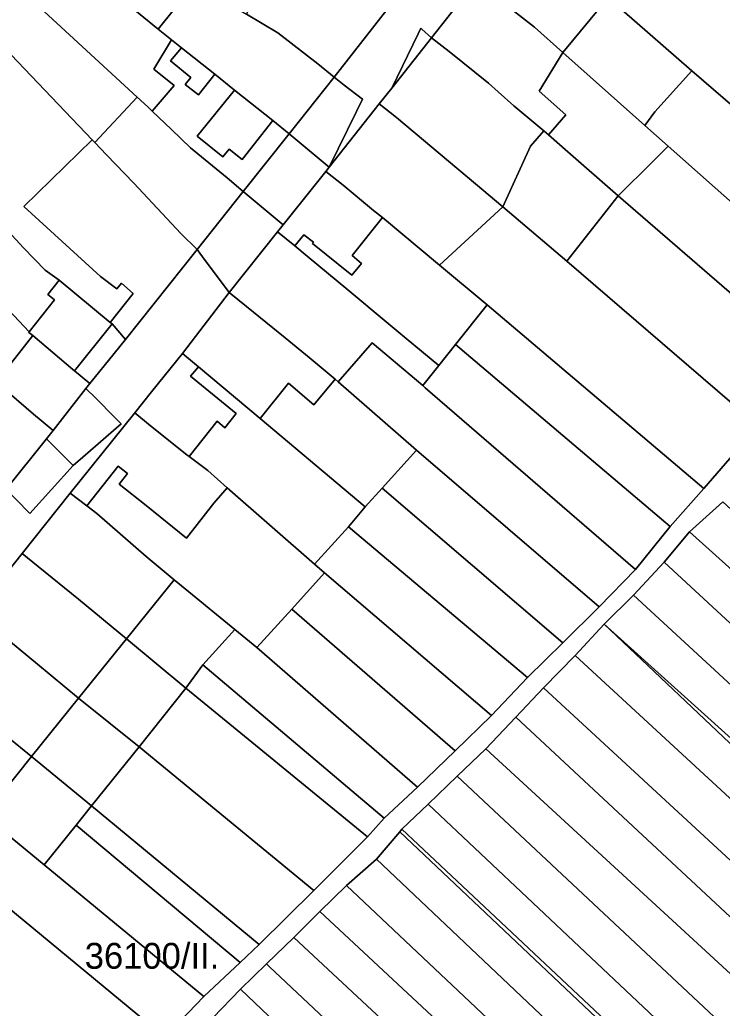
# Model space of a CAD drawing. Extents: x -537068 to -534056, y -1176840 to -1172401.
# Drawn here: x -535510.5 to -535374.6, y -1175812.5 to -1175621.4 of the extents above; entities that cross this region are included whole.
import ezdxf

# ---------------------------------------------------------------- set-up
doc = ezdxf.new("R2010")
doc.units = 0
for name, color, linetype in [('95560013', 7, 'Continuous'), ('95590013', 7, 'Continuous'), ('95610013', 7, 'Continuous'), ('95640013', 7, 'Continuous'), ('95660013', 7, 'Continuous')]:
    doc.layers.add(name, color=color, linetype=linetype)

msp = doc.modelspace()

# ---------------------------------------------------------------- linework, layer by layer
at = {"layer": '95560013'}
for points in [[(-535502.19, -1175597.34), (-535502.06, -1175597.17), (-535477.65, -1175615.63), (-535483.68, -1175623.22), (-535507.39, -1175603.91)], [(-535329.06, -1175662.73), (-535328.93, -1175662.85), (-535336.04, -1175669.84), (-535336.22, -1175669.68), (-535373.98, -1175636.94), (-535380.5, -1175631.28), (-535394.11, -1175619.48), (-535384.76, -1175608.85), (-535364.85, -1175626.56), (-535367.3, -1175629.34)], [(-535490.82, -1175672.36), (-535488.52, -1175674.32), (-535493.01, -1175679.93), (-535502.87, -1175671.76), (-535505.58, -1175669.81), (-535509.72, -1175665.5), (-535529.78, -1175643.79), (-535529.88, -1175643.69), (-535534.77, -1175638.56), (-535533.08, -1175636.42), (-535527.93, -1175629.9), (-535522.79, -1175623.39), (-535520.06, -1175619.94), (-535496.47, -1175644.61), (-535509.67, -1175657.5), (-535494.87, -1175671.04), (-535491.72, -1175673.47)], [(-535388.12, -1175648.87), (-535394.77, -1175655.48), (-535404.48, -1175646.96), (-535408.22, -1175643.69), (-535404.88, -1175639.8), (-535410.04, -1175635.24), (-535405.47, -1175627.73), (-535389.59, -1175641.84), (-535385.08, -1175645.85)], [(-535346.57, -1175680.03), (-535385.08, -1175645.85), (-535389.59, -1175641.84), (-535387.66, -1175639.2), (-535380.5, -1175631.28), (-535373.98, -1175636.94), (-535336.22, -1175669.68), (-535336.04, -1175669.84), (-535336.29, -1175670.08), (-535343.16, -1175677.96), (-535345.98, -1175680.56)], [(-535529.78, -1175643.79), (-535509.72, -1175665.5), (-535505.58, -1175669.81), (-535502.87, -1175671.76), (-535505.04, -1175674.53), (-535503.75, -1175675.55), (-535508.64, -1175681.77), (-535536.46, -1175652.23), (-535529.88, -1175643.69)], [(-535394.77, -1175655.48), (-535388.12, -1175648.87), (-535385.08, -1175645.85), (-535346.57, -1175680.03), (-535345.98, -1175680.56), (-535348.76, -1175683.14), (-535355.61, -1175689.31)], [(-535508.64, -1175681.77), (-535508.71, -1175681.86), (-535507.97, -1175682.48), (-535514.51, -1175690.8), (-535518.58, -1175686.14), (-535541.94, -1175659.8), (-535536.46, -1175652.23)], [(-535394.77, -1175655.48), (-535355.61, -1175689.31), (-535367.67, -1175699.94), (-535404.66, -1175668.06)], [(-535429.28, -1175668.86), (-535420.07, -1175676.55), (-535426.19, -1175684.18), (-535429.46, -1175688.27), (-535435.75, -1175683.03), (-535439.23, -1175680.14), (-535447.02, -1175673.66), (-535454.87, -1175667.13), (-535457.31, -1175665.14), (-535455.56, -1175662.97), (-535453.68, -1175664.42), (-535453.86, -1175664.66), (-535446.29, -1175670.81), (-535444.41, -1175668.51), (-535446.19, -1175667), (-535440.33, -1175659.64)], [(-535391.39, -1175727.68), (-535398.42, -1175734.92), (-535433.74, -1175704.6), (-535448.87, -1175691.41), (-535442.35, -1175683.85), (-535432.55, -1175692.13), (-535432.1, -1175692.57)], [(-535477.46, -1175690.33), (-535475.94, -1175688.5), (-535464.01, -1175698.5), (-535443.66, -1175715.55), (-535446.88, -1175719.44), (-535453.47, -1175726.66), (-535470.38, -1175711.9), (-535474.12, -1175708.55), (-535477.73, -1175705.86), (-535472.29, -1175699.02), (-535470.79, -1175700.28), (-535468.64, -1175697.54)], [(-535464.01, -1175698.5), (-535458.52, -1175691.68), (-535453.59, -1175695.83), (-535449.46, -1175690.92), (-535448.87, -1175691.41), (-535433.74, -1175704.6), (-535440.39, -1175711.94), (-535443.66, -1175715.55)], [(-535405.44, -1175741.83), (-535440.39, -1175711.94), (-535433.74, -1175704.6), (-535398.42, -1175734.92)], [(-535405.44, -1175741.83), (-535412.29, -1175748.56), (-535446.88, -1175719.44), (-535443.66, -1175715.55), (-535440.39, -1175711.94)], [(-535321.9, -1175763.11), (-535326.37, -1175769.45), (-535380.94, -1175720.41), (-535374.5, -1175714.58)], [(-535326.37, -1175769.45), (-535331.39, -1175776.57), (-535385.87, -1175726.27), (-535380.94, -1175720.41)], [(-535336.42, -1175783.7), (-535391.82, -1175732.67), (-535385.87, -1175726.27), (-535331.39, -1175776.57)], [(-535480.59, -1175729.65), (-535468.88, -1175739.3), (-535475.09, -1175746.08), (-535478.35, -1175750.65), (-535489.86, -1175741.1)], [(-535397.45, -1175738.23), (-535391.82, -1175732.67), (-535336.42, -1175783.7), (-535340.52, -1175789.52)], [(-535341.62, -1175791.07), (-535345.85, -1175797.07), (-535403.08, -1175744.29), (-535397.45, -1175738.23)], [(-535397.45, -1175738.23), (-535340.52, -1175789.52), (-535341.62, -1175791.07)], [(-535464.66, -1175742.78), (-535433.53, -1175769.76), (-535440.02, -1175775.76), (-535475.09, -1175746.08), (-535468.88, -1175739.3)], [(-535487.41, -1175761.95), (-535499.13, -1175752.55), (-535489.86, -1175741.1), (-535478.35, -1175750.65)], [(-535351.21, -1175804.11), (-535409.2, -1175750.56), (-535403.08, -1175744.29), (-535345.85, -1175797.07)], [(-535440.02, -1175775.76), (-535443.22, -1175779.35), (-535478.35, -1175750.65), (-535475.09, -1175746.08)], [(-535453.61, -1175789.75), (-535487.41, -1175761.95), (-535478.35, -1175750.65), (-535443.22, -1175779.35)], [(-535351.21, -1175804.11), (-535356.16, -1175810.6), (-535414.56, -1175756.25), (-535409.2, -1175750.56)], [(-535499.13, -1175752.55), (-535487.41, -1175761.95), (-535496.57, -1175773.36), (-535508.21, -1175763.84)], [(-535420.37, -1175762.32), (-535414.56, -1175756.25), (-535356.16, -1175810.6), (-535360.98, -1175816.94)], [(-535464.16, -1175800.19), (-535496.57, -1175773.36), (-535487.41, -1175761.95), (-535453.61, -1175789.75)], [(-535360.98, -1175816.94), (-535366.06, -1175823.6), (-535425.89, -1175767.64), (-535420.37, -1175762.32)], [(-535514.64, -1175777.45), (-535517.38, -1175775.25), (-535508.21, -1175763.84), (-535496.57, -1175773.36), (-535499.57, -1175777.1), (-535505.72, -1175784.77), (-535513.08, -1175778.7)], [(-535370.76, -1175830.27), (-535431.5, -1175773.03), (-535425.89, -1175767.64), (-535366.06, -1175823.6)], [(-535374.77, -1175835.95), (-535436.58, -1175777.9), (-535431.5, -1175773.03), (-535370.76, -1175830.27)], [(-535464.16, -1175800.19), (-535467.82, -1175803.62), (-535499.57, -1175777.1), (-535496.57, -1175773.36)], [(-535521.6, -1175785.74), (-535522.41, -1175785.07), (-535514.64, -1175777.45), (-535513.08, -1175778.7), (-535505.72, -1175784.77), (-535474.86, -1175810.24), (-535482.44, -1175818.09)], [(-535505.72, -1175784.77), (-535499.57, -1175777.1), (-535467.82, -1175803.62), (-535474.86, -1175810.24)], [(-535441.52, -1175783.7), (-535436.99, -1175778.38), (-535375.28, -1175836.68), (-535379.37, -1175842.48)], [(-535375.28, -1175836.68), (-535436.99, -1175778.38), (-535436.58, -1175777.9), (-535374.77, -1175835.95)], [(-535521.6, -1175785.74), (-535482.44, -1175818.09), (-535496.82, -1175832.93), (-535534.78, -1175801.99), (-535534.57, -1175801.74), (-535532.4, -1175799.03), (-535536.99, -1175795.45), (-535529.86, -1175786.33), (-535529.63, -1175786.51), (-535527.45, -1175783.8), (-535523.15, -1175787.49), (-535521.66, -1175785.8)], [(-535379.57, -1175842.76), (-535383.68, -1175848.73), (-535447.3, -1175788.74), (-535441.52, -1175783.7), (-535379.37, -1175842.48)], [(-535387.49, -1175854.29), (-535452.46, -1175793.8), (-535447.3, -1175788.74), (-535383.68, -1175848.73)], [(-535457.48, -1175798.84), (-535452.46, -1175793.8), (-535387.49, -1175854.29), (-535391.55, -1175860.18)], [(-535395.99, -1175866.64), (-535462.15, -1175804.48), (-535462.75, -1175803.92), (-535457.48, -1175798.84), (-535391.55, -1175860.18)], [(-535467.8, -1175808.78), (-535462.75, -1175803.92), (-535462.15, -1175804.48), (-535395.99, -1175866.64), (-535400.66, -1175872.73)], [(-535400.66, -1175872.73), (-535405.39, -1175878.91), (-535473.11, -1175814.36), (-535467.8, -1175808.78)]]:
    msp.add_lwpolyline(points, close=True, dxfattribs=at)
at = {"layer": '95590013'}
for points in [[(-535484.56, -1175630.96), (-535480.63, -1175634.11), (-535484.87, -1175639.07), (-535485.71, -1175638.27), (-535487.74, -1175636.4), (-535513.95, -1175612.21), (-535512.49, -1175610.36), (-535507.39, -1175603.91), (-535483.68, -1175623.22), (-535481.12, -1175625.3)], [(-535513.95, -1175612.21), (-535487.74, -1175636.4), (-535495.93, -1175645.18), (-535496.47, -1175644.61), (-535520.06, -1175619.94), (-535517.64, -1175616.88)], [(-535380.5, -1175631.28), (-535387.66, -1175639.2), (-535389.59, -1175641.84), (-535405.47, -1175627.73), (-535396.75, -1175617.18), (-535394.11, -1175619.48)], [(-535411.68, -1175645.88), (-535409.13, -1175642.89), (-535408.22, -1175643.69), (-535404.48, -1175646.96), (-535394.77, -1175655.48), (-535404.66, -1175668.06), (-535417.09, -1175657.56)], [(-535429.28, -1175668.86), (-535417.09, -1175657.56), (-535404.66, -1175668.06), (-535367.67, -1175699.94), (-535378.22, -1175712.03), (-535420.07, -1175676.55)], [(-535420.07, -1175676.55), (-535378.22, -1175712.03), (-535384.7, -1175719.38), (-535426.19, -1175684.18)], [(-535489.66, -1175709.15), (-535491.22, -1175711.16), (-535486.04, -1175715.34), (-535478.25, -1175721.62), (-535472.93, -1175714.85), (-535470.38, -1175711.9), (-535453.47, -1175726.66), (-535451.54, -1175728.34), (-535457.88, -1175735.32), (-535464.66, -1175742.78), (-535468.88, -1175739.3), (-535480.59, -1175729.65), (-535486.01, -1175725.18), (-535495.59, -1175716.84), (-535497.51, -1175715.38), (-535491.45, -1175707.71)], [(-535457.88, -1175735.32), (-535451.54, -1175728.34), (-535419.26, -1175755.91), (-535426.29, -1175762.73)], [(-535457.88, -1175735.32), (-535426.29, -1175762.73), (-535433.53, -1175769.76), (-535464.66, -1175742.78)]]:
    msp.add_lwpolyline(points, close=True, dxfattribs=at)
at = {"layer": '95610013'}
for points in [[(-535432.1, -1175692.57), (-535432.55, -1175692.13), (-535429.46, -1175688.27), (-535426.19, -1175684.18), (-535384.7, -1175719.38), (-535391.39, -1175727.68)], [(-535451.54, -1175728.34), (-535453.47, -1175726.66), (-535446.88, -1175719.44), (-535412.29, -1175748.56), (-535419.26, -1175755.91)]]:
    msp.add_lwpolyline(points, close=True, dxfattribs=at)
at = {"layer": '95640013'}
for points in [[(-535418.8, -1175616.67), (-535422.2, -1175613.99), (-535420.85, -1175612.3), (-535416.14, -1175606.37), (-535413.46, -1175602.99), (-535410.19, -1175605.76), (-535408.21, -1175607.44), (-535402.51, -1175612.19), (-535396.75, -1175617.18), (-535405.47, -1175627.73), (-535410.96, -1175622.85)], [(-535466.62, -1175620.38), (-535458.78, -1175605.84), (-535457.08, -1175606.91), (-535450.36, -1175610.98), (-535442.6, -1175617.01), (-535439.48, -1175619.54), (-535449.7, -1175632.54), (-535452.86, -1175629.97), (-535460.55, -1175623.96)], [(-535427.46, -1175627.56), (-535430.88, -1175624.91), (-535426.01, -1175618.78), (-535422.2, -1175613.99), (-535418.8, -1175616.67), (-535410.96, -1175622.85), (-535405.47, -1175627.73), (-535410.04, -1175635.24), (-535404.88, -1175639.8), (-535408.22, -1175643.69), (-535409.13, -1175642.89), (-535414.94, -1175638.06), (-535417.96, -1175635.35), (-535419.82, -1175633.67)], [(-535483.68, -1175623.22), (-535477.65, -1175615.63), (-535473.74, -1175616.19), (-535469.62, -1175618.62), (-535466.62, -1175620.38), (-535460.55, -1175623.96), (-535452.86, -1175629.97), (-535449.7, -1175632.54), (-535458.37, -1175643.45), (-535461.54, -1175640.91), (-535468.96, -1175635.02), (-535472.76, -1175631.98), (-535479.21, -1175626.83), (-535481.12, -1175625.3)], [(-535430.88, -1175624.91), (-535438.55, -1175634.63), (-535433.45, -1175624.14), (-535432.93, -1175623.08), (-535432.74, -1175623.25)], [(-535467.24, -1175654.63), (-535470.36, -1175651.98), (-535477.44, -1175646.21), (-535481.16, -1175642.64), (-535484.87, -1175639.07), (-535480.63, -1175634.11), (-535484.56, -1175630.96), (-535481.12, -1175625.3), (-535479.21, -1175626.83), (-535481.31, -1175629.4), (-535477.37, -1175632.58), (-535478.47, -1175633.96), (-535475.91, -1175635.95), (-535472.76, -1175631.98), (-535468.96, -1175635.02), (-535476.19, -1175643.92), (-535471.19, -1175647.95), (-535470, -1175646.42), (-535467.48, -1175648.44), (-535461.54, -1175640.91), (-535458.37, -1175643.45)], [(-535437.62, -1175640.34), (-535440.97, -1175637.7), (-535438.55, -1175634.63), (-535430.88, -1175624.91), (-535427.46, -1175627.56), (-535419.82, -1175633.67), (-535417.96, -1175635.35), (-535414.94, -1175638.06), (-535409.13, -1175642.89), (-535411.68, -1175645.88), (-535417.09, -1175657.56), (-535422.33, -1175653.13)], [(-535479.21, -1175626.83), (-535472.76, -1175631.98), (-535475.91, -1175635.95), (-535478.47, -1175633.96), (-535477.37, -1175632.58), (-535481.31, -1175629.4)], [(-535450.62, -1175649.93), (-535452.58, -1175648.29), (-535456.43, -1175645.07), (-535458.37, -1175643.45), (-535449.7, -1175632.54), (-535447.71, -1175634.08), (-535444.19, -1175636.81), (-535445.33, -1175639.14)], [(-535468.96, -1175635.02), (-535461.54, -1175640.91), (-535467.48, -1175648.44), (-535470, -1175646.42), (-535471.19, -1175647.95), (-535476.19, -1175643.92)], [(-535493.68, -1175647.56), (-535495.93, -1175645.18), (-535487.74, -1175636.4), (-535485.71, -1175638.27), (-535484.87, -1175639.07), (-535481.16, -1175642.64), (-535477.44, -1175646.21), (-535470.36, -1175651.98), (-535467.24, -1175654.63), (-535476.18, -1175665.83), (-535479.34, -1175662.74), (-535488.43, -1175653.04)], [(-535437.62, -1175640.34), (-535422.33, -1175653.13), (-535417.09, -1175657.56), (-535429.28, -1175668.86), (-535440.33, -1175659.64), (-535442.09, -1175658.27), (-535447.91, -1175653.43), (-535451.29, -1175650.78), (-535450.62, -1175649.93), (-535440.97, -1175637.7)], [(-535493.68, -1175647.56), (-535488.43, -1175653.04), (-535479.34, -1175662.74), (-535476.18, -1175665.83), (-535490.03, -1175683.21), (-535492.62, -1175680.21), (-535493.01, -1175679.93), (-535488.52, -1175674.32), (-535490.82, -1175672.36), (-535491.72, -1175673.47), (-535494.87, -1175671.04), (-535509.67, -1175657.5), (-535496.47, -1175644.61), (-535495.93, -1175645.18)], [(-535461.45, -1175659.48), (-535465.31, -1175656.25), (-535467.24, -1175654.63), (-535458.37, -1175643.45), (-535456.43, -1175645.07), (-535452.58, -1175648.29), (-535450.62, -1175649.93), (-535451.29, -1175650.78), (-535459.55, -1175661.07)], [(-535453.68, -1175664.42), (-535455.56, -1175662.97), (-535457.31, -1175665.14), (-535460.64, -1175662.42), (-535459.55, -1175661.07), (-535451.29, -1175650.78), (-535447.91, -1175653.43), (-535442.09, -1175658.27), (-535440.33, -1175659.64), (-535446.19, -1175667), (-535444.41, -1175668.51), (-535446.29, -1175670.81), (-535453.86, -1175664.66)], [(-535459.55, -1175661.07), (-535460.64, -1175662.42), (-535470.01, -1175674.15), (-535471.49, -1175672.16), (-535474.6, -1175667.96), (-535476.18, -1175665.83), (-535467.24, -1175654.63), (-535465.31, -1175656.25), (-535461.45, -1175659.48)], [(-535435.75, -1175683.03), (-535429.46, -1175688.27), (-535432.55, -1175692.13), (-535442.35, -1175683.85), (-535448.87, -1175691.41), (-535449.46, -1175690.92), (-535454.54, -1175686.73), (-535459.13, -1175682.93), (-535466.6, -1175676.86), (-535470.01, -1175674.15), (-535460.64, -1175662.42), (-535457.31, -1175665.14), (-535454.87, -1175667.13), (-535447.02, -1175673.66), (-535439.23, -1175680.14)], [(-535493.01, -1175679.93), (-535492.62, -1175680.21), (-535499.86, -1175689.29), (-535500.2, -1175689.02), (-535507.97, -1175682.48), (-535508.71, -1175681.86), (-535508.64, -1175681.77), (-535503.75, -1175675.55), (-535505.04, -1175674.53), (-535502.87, -1175671.76)], [(-535475.94, -1175688.5), (-535479.01, -1175685.92), (-535470.01, -1175674.15), (-535466.6, -1175676.86), (-535459.13, -1175682.93), (-535454.54, -1175686.73), (-535449.46, -1175690.92), (-535453.59, -1175695.83), (-535458.52, -1175691.68), (-535464.01, -1175698.5)], [(-535499.86, -1175689.29), (-535492.62, -1175680.21), (-535490.03, -1175683.21), (-535492.21, -1175685.91), (-535496.93, -1175691.74)], [(-535507.11, -1175698.26), (-535507.36, -1175698.04), (-535514.89, -1175691.59), (-535514.29, -1175691.06), (-535514.51, -1175690.8), (-535507.97, -1175682.48), (-535500.2, -1175689.02), (-535499.86, -1175689.29), (-535496.93, -1175691.74), (-535497.68, -1175692.7), (-535504.04, -1175700.82)], [(-535530.1, -1175685.11), (-535526.17, -1175689.23), (-535524.11, -1175691.5), (-535523.33, -1175690.47), (-535518.58, -1175686.14), (-535514.51, -1175690.8), (-535514.29, -1175691.06), (-535514.89, -1175691.59), (-535507.36, -1175698.04), (-535507.11, -1175698.26), (-535504.04, -1175700.82), (-535505.33, -1175702.44), (-535513.12, -1175712.17), (-535516.19, -1175709.64), (-535519.95, -1175705.59), (-535522.8, -1175702.66), (-535525.76, -1175699.59), (-535535.03, -1175689.74)], [(-535470.79, -1175700.28), (-535472.29, -1175699.02), (-535477.73, -1175705.86), (-535478.17, -1175705.53), (-535485.16, -1175699.89), (-535488.25, -1175697.39), (-535484.99, -1175693.35), (-535479.01, -1175685.92), (-535475.94, -1175688.5), (-535477.46, -1175690.33), (-535468.64, -1175697.54)], [(-535503.46, -1175704.31), (-535505.33, -1175702.44), (-535504.04, -1175700.82), (-535497.68, -1175692.7), (-535495.76, -1175694.6), (-535492.13, -1175698.21), (-535490.83, -1175699.5), (-535498.28, -1175705.98), (-535500.16, -1175707.61)], [(-535497.51, -1175715.38), (-535500.75, -1175712.91), (-535488.25, -1175697.39), (-535485.16, -1175699.89), (-535478.17, -1175705.53), (-535477.73, -1175705.86), (-535474.12, -1175708.55), (-535470.38, -1175711.9), (-535472.93, -1175714.85), (-535478.25, -1175721.62), (-535486.04, -1175715.34), (-535491.22, -1175711.16), (-535489.66, -1175709.15), (-535491.45, -1175707.71)], [(-535500.16, -1175707.61), (-535508.5, -1175716.89), (-535511.24, -1175714.09), (-535513.12, -1175712.17), (-535505.33, -1175702.44), (-535503.46, -1175704.31)], [(-535495.59, -1175716.84), (-535486.01, -1175725.18), (-535480.59, -1175729.65), (-535489.86, -1175741.1), (-535499.1, -1175733.42), (-535506.89, -1175727.13), (-535510.03, -1175724.59), (-535500.75, -1175712.91), (-535497.51, -1175715.38)], [(-535516.09, -1175738.54), (-535519.13, -1175736.05), (-535510.03, -1175724.59), (-535506.89, -1175727.13), (-535499.1, -1175733.42), (-535489.86, -1175741.1), (-535499.13, -1175752.55), (-535507.06, -1175745.95)], [(-535516.09, -1175738.54), (-535507.06, -1175745.95), (-535499.13, -1175752.55), (-535508.21, -1175763.84), (-535517.39, -1175756.34), (-535517.7, -1175756.09), (-535525.24, -1175750.03), (-535528.31, -1175747.61), (-535519.13, -1175736.05)], [(-535525.24, -1175750.03), (-535517.7, -1175756.09), (-535517.39, -1175756.34), (-535508.21, -1175763.84), (-535517.38, -1175775.25), (-535519.76, -1175773.35), (-535534.45, -1175761.46), (-535537.36, -1175759.04), (-535528.31, -1175747.61)]]:
    msp.add_lwpolyline(points, close=True, dxfattribs=at)
for points in [[(-535426.01, -1175618.78), (-535430.88, -1175624.91), (-535432.74, -1175623.25), (-535432.93, -1175623.08), (-535433.45, -1175624.14), (-535438.55, -1175634.63), (-535440.97, -1175637.7), (-535450.62, -1175649.93), (-535445.33, -1175639.14), (-535444.19, -1175636.81), (-535447.71, -1175634.08), (-535449.7, -1175632.54), (-535439.48, -1175619.54)], [(-535511.24, -1175714.09), (-535508.5, -1175716.89), (-535500.16, -1175707.61), (-535498.28, -1175705.98), (-535490.83, -1175699.5), (-535492.13, -1175698.21), (-535495.76, -1175694.6), (-535497.68, -1175692.7), (-535496.93, -1175691.74), (-535492.21, -1175685.91), (-535490.03, -1175683.21), (-535476.18, -1175665.83), (-535474.6, -1175667.96), (-535471.49, -1175672.16), (-535470.01, -1175674.15), (-535479.01, -1175685.92), (-535484.99, -1175693.35), (-535488.25, -1175697.39), (-535500.75, -1175712.91), (-535510.03, -1175724.59), (-535519.13, -1175736.05)], [(-535482.44, -1175818.09), (-535474.86, -1175810.24), (-535467.82, -1175803.62), (-535464.16, -1175800.19), (-535453.61, -1175789.75), (-535443.22, -1175779.35), (-535440.02, -1175775.76), (-535433.53, -1175769.76), (-535426.29, -1175762.73), (-535419.26, -1175755.91), (-535412.29, -1175748.56), (-535405.44, -1175741.83), (-535398.42, -1175734.92), (-535391.39, -1175727.68), (-535384.7, -1175719.38), (-535378.22, -1175712.03), (-535367.67, -1175699.94)], [(-535374.5, -1175714.58), (-535380.94, -1175720.41), (-535385.87, -1175726.27), (-535391.82, -1175732.67), (-535397.45, -1175738.23), (-535403.08, -1175744.29), (-535409.2, -1175750.56), (-535414.56, -1175756.25), (-535420.37, -1175762.32), (-535425.89, -1175767.64), (-535431.5, -1175773.03), (-535436.58, -1175777.9), (-535436.99, -1175778.38), (-535441.52, -1175783.7), (-535447.3, -1175788.74), (-535452.46, -1175793.8), (-535457.48, -1175798.84), (-535462.75, -1175803.92), (-535467.8, -1175808.78), (-535473.11, -1175814.36)]]:
    msp.add_lwpolyline(points, dxfattribs=at)

# ---------------------------------------------------------------- texts
at = {"layer": '95660013'}
msp.add_text('36100/II.', height=5, rotation=360, dxfattribs=at).set_placement((-535497.91, -1175804.85))

doc.saveas('drawing.dxf')
